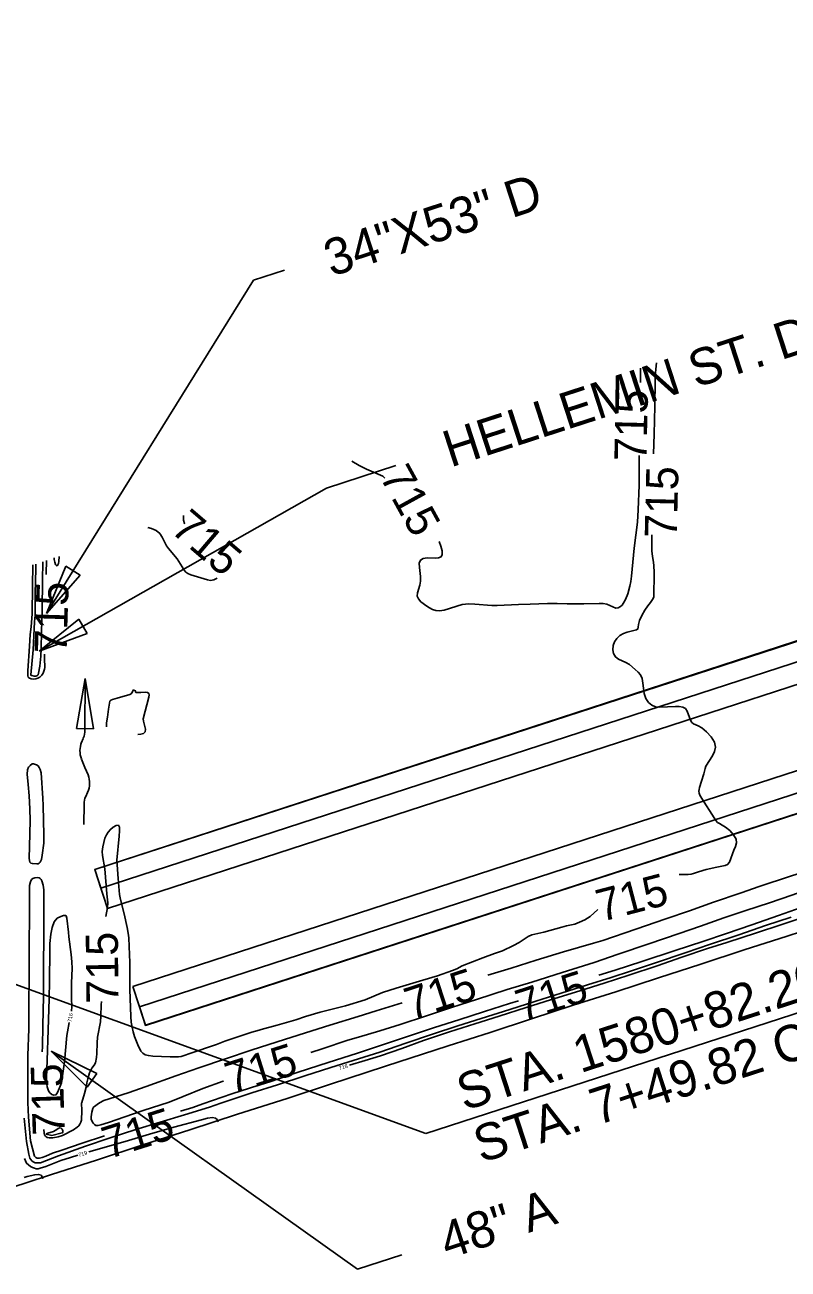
# Model space of a CAD drawing. Extents: x -468563856 to 36492962, y -306094093 to 11899197.
# Drawn here: x 1824382 to 1825166, y 531760 to 533036 of the extents above; entities that cross this region are included whole.
import ezdxf

# ---------------------------------------------------------------- set-up
doc = ezdxf.new("R2010")
doc.units = 0
for name, color, linetype in [('Default', 7, 'Continuous'), ('DT_X_Contour_Minor', 7, 'Continuous'), ('Level 14', 7, 'Continuous'), ('Level 19', 7, 'Continuous'), ('Level 31', 7, 'Continuous'), ('Level 40', 7, 'Continuous'), ('SC_Shading3', 7, 'Continuous')]:
    doc.layers.add(name, color=color, linetype=linetype)

msp = doc.modelspace()

# ---------------------------------------------------------------- linework, layer by layer
at = {"layer": 'Default'}
for points in [[(1824453.9, 532170), (1824460.1, 532150.9), (1827123.3, 533015.5), (1827116.5, 533036.4)], [(1824499.7, 532029.1), (1824505.9, 532010), (1827169, 532874.6), (1827162.8, 532893.7)]]:
    msp.add_lwpolyline(points, close=True, dxfattribs=at)
at = {"layer": 'DT_X_Contour_Minor'}
for points in [[(1825030.7, 532689.6), (1825029.7, 532679.8), (1825029.2, 532671), (1825028.7, 532645.4), (1825028.2, 532616.5), (1825027.6, 532596.3)], [(1825014, 532669.6), (1825014.2, 532677.5), (1825014.3, 532684.3)], [(1825013.6, 532650.8), (1825013.6, 532651.6)], [(1824717.8, 532588.8), (1824725.2, 532584.3), (1824732.7, 532580.6), (1824749.7, 532573.6), (1824751.8, 532571.3)], [(1824807.5, 532506.3), (1824809.3, 532501.7), (1824810.6, 532496.8), (1824810.6, 532493.2), (1824809.4, 532490.8), (1824806.9, 532489.7), (1824803.5, 532489.4), (1824795, 532489.6), (1824791, 532489), (1824788.1, 532487.3), (1824787, 532484.1), (1824787.1, 532479.9), (1824788.1, 532470.4), (1824788.2, 532465.8), (1824787.6, 532461.5), (1824785.1, 532453.8), (1824784.8, 532450.5), (1824786.1, 532447.5), (1824788.6, 532444.7), (1824794.6, 532440.1), (1824797.6, 532438.3), (1824800.6, 532436.8), (1824804, 532435.8), (1824807.9, 532435.4), (1824812.6, 532436.1), (1824831.2, 532441.7), (1824837.8, 532442.4), (1824844.2, 532442.3), (1824861.6, 532440.9), (1824866.9, 532440.8), (1824888.9, 532441.9), (1824900.8, 532442), (1824918.5, 532443), (1824928.5, 532442.7), (1824938.8, 532442.4), (1824956.1, 532442.6), (1824971.6, 532443), (1824975.7, 532442.8), (1824979.4, 532442), (1824988.9, 532438), (1824991.3, 532438.3), (1824993.5, 532439.6), (1824995.2, 532441.2), (1824996.5, 532442.9), (1824998.7, 532446.9), (1825001.1, 532452.9), (1825003.3, 532460.7), (1825004.2, 532465.3), (1825004.9, 532470.8), (1825007.7, 532499.6), (1825010.9, 532526.4), (1825011.7, 532538.9), (1825012.6, 532564.3), (1825012.7, 532579.1), (1825012.7, 532594.6)], [(1824546.2, 532524.5), (1824545.9, 532524.8), (1824545.1, 532528.3), (1824545.1, 532533)], [(1824508.2, 532520.9), (1824512.2, 532519.8), (1824517, 532517.6), (1824520.5, 532514.5), (1824522.9, 532510.9), (1824527.5, 532501.9), (1824529.5, 532499.3), (1824538.5, 532488.6), (1824543.6, 532480.3), (1824545.6, 532477), (1824547.4, 532474.9), (1824549.4, 532473.5), (1824552.3, 532472.4), (1824569.7, 532467), (1824572.8, 532466.5), (1824576, 532467.1), (1824579.5, 532468.8)], [(1825025.8, 532513.2), (1825025.7, 532505.2), (1825025.9, 532496.7), (1825026.4, 532491.2), (1825027.2, 532487.2), (1825027.8, 532482.1), (1825028.1, 532474.4), (1825027.8, 532449.6), (1825027.3, 532447.8), (1825024.4, 532444), (1825021.8, 532440.6), (1825018.6, 532435.9), (1825015.5, 532430.4), (1825013.1, 532425.3), (1825012.2, 532421.3), (1825011.9, 532418.5), (1825011.4, 532416.7), (1825009.9, 532415.7), (1825000.5, 532413.5), (1824996.6, 532412), (1824993, 532409.9), (1824989.9, 532407), (1824987.6, 532403.5), (1824986.1, 532399.6), (1824985.7, 532395.4), (1824986.4, 532391.4), (1824988.3, 532388.1), (1824991.4, 532385.8), (1824999.2, 532382.3), (1825002.7, 532380.2), (1825008.8, 532375.1), (1825011.6, 532372.5), (1825014.1, 532369.5), (1825015.8, 532365.8), (1825016.6, 532361.2), (1825017.1, 532355.9), (1825017.9, 532350.5), (1825019.7, 532345.5), (1825022.3, 532341.3), (1825025.7, 532338.4), (1825029.6, 532336.9), (1825033.7, 532336.6), (1825050.1, 532337.1), (1825054, 532337.1), (1825057.6, 532336.5), (1825060.4, 532335.1), (1825062.2, 532332.5), (1825065.5, 532323.1), (1825067, 532320.9), (1825068.7, 532319.5), (1825073.4, 532317.4), (1825077.1, 532315.2), (1825081.8, 532311.2), (1825086.6, 532306.2), (1825090, 532300.7), (1825091, 532295.6), (1825090.2, 532291), (1825088.1, 532286.6), (1825081.3, 532276), (1825080.4, 532273.5), (1825079.3, 532268.2), (1825076.9, 532260.6), (1825074.7, 532254.1), (1825074.2, 532251.9), (1825074.1, 532250.2), (1825074.3, 532248.4), (1825075.2, 532246.2), (1825077.1, 532242.8), (1825089.7, 532223.1), (1825091.4, 532220.3), (1825093.1, 532218.3), (1825095.1, 532217), (1825097.9, 532215.6), (1825101.4, 532213.3), (1825105.7, 532209.8), (1825109.7, 532205.5), (1825112.3, 532201.1), (1825112.7, 532197.2), (1825111.5, 532193.6), (1825109.8, 532189.7), (1825105.4, 532177.4), (1825103.6, 532175.1), (1825101, 532173.9), (1825092.4, 532172.2), (1825081.6, 532170.1), (1825073.7, 532167.7), (1825068.5, 532165.8), (1825066, 532165.2), (1825063.1, 532164.9), (1825053.9, 532164.7)], [(1824393.2, 532483.3), (1824393.2, 532478.3), (1824392.8, 532453.2), (1824392.7, 532430.7), (1824392.1, 532424.1), (1824390.7, 532395.4), (1824388.2, 532369.7), (1824388.5, 532369.1), (1824389.3, 532368.8), (1824391.7, 532368.4), (1824393.5, 532368.4), (1824395, 532369), (1824395.6, 532369.7), (1824396.1, 532371.2), (1824397.3, 532378.5), (1824398.4, 532388.7), (1824398.7, 532396.5), (1824399.3, 532413.7), (1824400, 532436.7), (1824400.2, 532466.5), (1824400.5, 532485.7)], [(1824403.9, 532472.6), (1824403.9, 532473.6), (1824404.2, 532486.9)], [(1824412.3, 532489.6), (1824412.3, 532488.1), (1824412.8, 532485.2), (1824413.6, 532483), (1824414.4, 532481.7), (1824415.2, 532481.6), (1824416, 532482.5), (1824416.6, 532484), (1824417, 532486), (1824417.4, 532490.9), (1824417.4, 532491.2)], [(1824390.3, 532482.4), (1824389.9, 532460.7), (1824389.5, 532432.4), (1824388.4, 532419), (1824387.6, 532411.1), (1824386.8, 532398.9), (1824385.1, 532373.9), (1824385.2, 532368.6), (1824385.5, 532367.4), (1824386.2, 532366.7), (1824388.4, 532365.7), (1824390.6, 532365.2), (1824393.3, 532365.5), (1824395.4, 532366.1), (1824397.6, 532367.3), (1824399.4, 532369.2), (1824400.8, 532371.5), (1824402.3, 532375.3), (1824402.6, 532377.3), (1824402.4, 532386.4), (1824402.4, 532390.9)], [(1824465.9, 532316.4), (1824465.9, 532316.4), (1824466, 532320.4), (1824466.8, 532326.2), (1824468.1, 532334.3), (1824469.2, 532342.7), (1824470.5, 532343.5), (1824472.2, 532344.3), (1824476.8, 532345.8), (1824489.9, 532349.4), (1824491.1, 532350.3), (1824492.5, 532352.1), (1824493.2, 532353.9), (1824493.2, 532354.1), (1824494, 532354), (1824495.7, 532353.2), (1824495.7, 532352.3), (1824496.1, 532351.7), (1824497.1, 532351.4), (1824501.3, 532351.6), (1824506.1, 532351.8), (1824508, 532351.4), (1824509.2, 532350.6), (1824509.6, 532349), (1824509.3, 532346.6), (1824503.6, 532324.5), (1824503.8, 532322.1), (1824505.9, 532313.9), (1824505.5, 532311.3), (1824503.8, 532309.6), (1824501, 532308.7), (1824498.2, 532308.5)], [(1824401.6, 532197), (1824401.5, 532205.3), (1824401, 532235.6), (1824400.6, 532243.2), (1824398.7, 532269.2), (1824397.7, 532272.7), (1824396.8, 532274.7), (1824395.6, 532276.4), (1824393.9, 532277.4), (1824390.9, 532278.2), (1824389.5, 532278.2), (1824387.4, 532276.8), (1824385.9, 532275.1), (1824384.8, 532272.1), (1824384.5, 532267.6), (1824385.3, 532257.3), (1824386.5, 532245.5), (1824387.2, 532232.1), (1824387.4, 532220.3), (1824386.9, 532193.7), (1824386.6, 532181.6), (1824386.8, 532179.1), (1824387.3, 532177.5), (1824388.3, 532176.5), (1824389.9, 532176), (1824394.4, 532175.7), (1824395.7, 532175.9), (1824396.7, 532176.3), (1824397.9, 532177.6), (1824399, 532180.2), (1824400, 532184.5), (1824401.6, 532197)], [(1824970.3, 532128.8), (1824962.3, 532121.8), (1824957, 532118.4), (1824951.6, 532115.8), (1824946.6, 532114), (1824938, 532112), (1824933.2, 532110.9), (1824914.9, 532105.5), (1824902.7, 532103), (1824898.9, 532101.1), (1824889.5, 532095.2), (1824883.6, 532092), (1824872.3, 532086.6), (1824864.4, 532083.7), (1824852.3, 532079.3), (1824830.9, 532071.1), (1824825.7, 532068.2), (1824821.1, 532066.3), (1824805.7, 532061), (1824790.8, 532056.4), (1824763.3, 532048.1), (1824749.2, 532043.7), (1824731.3, 532036.1), (1824711.1, 532030.2), (1824685.2, 532023.6), (1824670.2, 532019.3), (1824660.1, 532015.7), (1824641.1, 532010.1), (1824624.6, 532005.7), (1824622.6, 532005.3), (1824615.2, 532003), (1824587.5, 531993.9), (1824578.7, 531990.5), (1824575.7, 531989.3), (1824554.5, 531982.1), (1824542.4, 531978.2), (1824539.6, 531977.7), (1824531.4, 531977.9), (1824513.3, 531978.6), (1824508.9, 531979), (1824505.5, 531979.9), (1824503.1, 531981.5), (1824501.3, 531983.7), (1824498.1, 531990.2), (1824494.7, 531998.7), (1824493.3, 532003.3), (1824492.1, 532008.2), (1824491.3, 532013.5), (1824490.8, 532019.3), (1824489.8, 532046.8), (1824489.9, 532074.5), (1824489.3, 532090.8), (1824488.7, 532099.9), (1824488.1, 532104.7), (1824487.1, 532110.5), (1824483.9, 532124.6), (1824480.1, 532139.1), (1824479.3, 532144.4), (1824478, 532160.8), (1824476.6, 532179.4), (1824478.8, 532204.3), (1824479.2, 532209.7), (1824479.2, 532213.5), (1824478.2, 532215.4), (1824475.9, 532215.2), (1824472.8, 532213.4), (1824469.9, 532211), (1824467.5, 532208.4), (1824465.8, 532205.5), (1824464.3, 532202), (1824463, 532197.8), (1824462, 532193.1), (1824461.6, 532188.5), (1824461.8, 532184.4), (1824464.2, 532170.5), (1824466.3, 532145), (1824467.1, 532135.9), (1824466.8, 532131.1), (1824465.2, 532121.8)], [(1825294.3, 532204.6), (1825267.4, 532195.2), (1825252.1, 532190.1), (1825225.1, 532181.4), (1825201.2, 532173.8), (1825168, 532163.2), (1825135.9, 532152.4), (1825117.5, 532146.1), (1825089.2, 532136.3), (1825064.5, 532127.7), (1825040.2, 532119.3), (1825009.5, 532108.7), (1824975.4, 532097.2), (1824965.9, 532094.3), (1824935.2, 532085.6), (1824907, 532077), (1824881.2, 532068.9), (1824857.3, 532061.4)], [(1824971.2, 532061.4), (1824988, 532066.8), (1825015.5, 532075.7), (1825049.8, 532086.9), (1825078, 532096.2), (1825102.3, 532104.2), (1825128.5, 532113.1), (1825155.7, 532122.9), (1825173.4, 532129), (1825200.8, 532137.9), (1825227.3, 532146.3), (1825257.6, 532155.7), (1825283.3, 532163.7), (1825312.1, 532172.7), (1825317.1, 532174.3)], [(1824400, 531982.8), (1824400.1, 531988.5), (1824400.6, 532009.5), (1824401.2, 532039.9), (1824401.3, 532073), (1824401.5, 532100), (1824401.6, 532127.3), (1824401.4, 532149), (1824400.8, 532153.8), (1824399.5, 532158.3), (1824398.7, 532159.8), (1824397.9, 532160.8), (1824396.9, 532161.4), (1824394.6, 532161.7), (1824392.3, 532161.5), (1824390.2, 532160.8), (1824388.8, 532159.6), (1824387.7, 532157.3), (1824387, 532153.7), (1824386.8, 532144.7), (1824386.7, 532124.2), (1824386.4, 532092.1), (1824386.4, 532059.9), (1824386.3, 532031.7), (1824386, 532006.6), (1824385.2, 531979), (1824385, 531960), (1824385.2, 531931.1), (1824385.7, 531916), (1824387.8, 531891.6), (1824392, 531875.9), (1824393.5, 531874.5), (1824394.6, 531874), (1824397, 531873.9), (1824400, 531874.5), (1824403.6, 531876), (1824410.3, 531878.8), (1824420, 531882.1), (1824440.9, 531889.2), (1824463.7, 531896.8)], [(1824675.7, 531982.2), (1824687.4, 531986), (1824713.8, 531994.8), (1824724.6, 531998), (1824746.6, 532004.3), (1824767.4, 532011), (1824794.4, 532020), (1824820.2, 532028.4), (1824845.8, 532036.7), (1824877.2, 532046.7), (1824902.6, 532054.5), (1824933.7, 532064.3), (1824966.4, 532074.7), (1824991.3, 532083), (1825022.8, 532093.6), (1825053.9, 532104.4), (1825075.6, 532111.9), (1825099.8, 532120.5), (1825122.2, 532127.8), (1825146.5, 532135.7), (1825169.4, 532143.7), (1825186, 532149.3)], [(1824715.4, 531969.2), (1824731.5, 531974), (1824747.1, 531978.9), (1824769, 531986.5), (1824791.5, 531994.4), (1824818.2, 532003.5), (1824843.9, 532011.5), (1824869, 532019.5), (1824896.9, 532028.5), (1824921.9, 532036.3), (1824951.7, 532045.5), (1824977, 532053.4), (1825002.3, 532061.5), (1825031.2, 532071.3), (1825056.4, 532080), (1825082.8, 532088.8), (1825102.7, 532095.1), (1825133.1, 532105), (1825158.2, 532113.2), (1825183.8, 532121.7), (1825210.8, 532130.8), (1825215.4, 532132.3)], [(1825168.8, 532121), (1825142.6, 532112.4), (1825115.1, 532103), (1825085, 532092.9), (1825060.9, 532084.8), (1825029.4, 532074.3), (1825004.9, 532066), (1824983.9, 532059.1), (1824959.7, 532051.5), (1824932.6, 532043), (1824906.7, 532035), (1824879.9, 532026.5), (1824850.7, 532017.2), (1824826.5, 532009.6), (1824800.6, 532001.1), (1824773.3, 531991.9), (1824746.6, 531982.7), (1824719.1, 531973.9), (1824696.1, 531966.7), (1824669.4, 531958.2), (1824641.5, 531949.2), (1824615.2, 531940.8), (1824583.4, 531930.2), (1824571.5, 531926.3), (1824545.8, 531918.4), (1824521.1, 531910.8), (1824496.1, 531903.1), (1824468.7, 531894.2), (1824444.4, 531886.1), (1824416.7, 531876.3), (1824398.1, 531869.1), (1824394.5, 531868.9), (1824392.5, 531869.2), (1824390.7, 531870), (1824389.2, 531871.1), (1824388.1, 531872.5), (1824387.3, 531874), (1824386.3, 531877.8), (1824383.6, 531891), (1824381.4, 531914.8)], [(1824429.8, 532024.7), (1824430.2, 532029.3), (1824430.1, 532037.5), (1824429.8, 532053.8), (1824430.5, 532068.4), (1824430.4, 532075.4), (1824429.7, 532082.6), (1824427.3, 532100.9), (1824427, 532105.5), (1824425.2, 532120), (1824424.6, 532122.3), (1824423.7, 532122.9), (1824421.8, 532122.6), (1824418.9, 532121.8), (1824415.3, 532119.9), (1824412.2, 532116.2), (1824410, 532110.4), (1824408.7, 532103.7), (1824407.7, 532094), (1824407.6, 532086.1), (1824407.5, 532055.7), (1824407.1, 532037.2), (1824406, 532005.4), (1824404.8, 531974.1), (1824404.4, 531956.6), (1824404.6, 531949.7), (1824405, 531947.1), (1824405.5, 531944.8), (1824406.4, 531942.8), (1824407.8, 531940.9), (1824409.7, 531939.3), (1824411.9, 531938.4), (1824413.9, 531938.7), (1824415.4, 531940.4), (1824417.6, 531945.9), (1824419, 531949.5), (1824419.8, 531951), (1824422.8, 531972.7), (1824425.3, 531999.7), (1824425.9, 532003.4), (1824427.7, 532012.9)], [(1824460.7, 532034.5), (1824460.5, 532031.2), (1824460.1, 532019.4), (1824459.6, 532013.6), (1824456.7, 531997.8), (1824456.3, 531992.1), (1824456, 531981.2), (1824455.6, 531977.1), (1824454.5, 531971.7), (1824453.2, 531969.2), (1824450.8, 531966), (1824448.6, 531961.2), (1824446.6, 531955.2), (1824445.8, 531951.1), (1824444.9, 531946.5), (1824443.3, 531940.3), (1824440.4, 531931.1), (1824440.1, 531930.1), (1824440.5, 531922.7), (1824440.1, 531912.8), (1824439.6, 531910.7), (1824438.6, 531908.8), (1824437.4, 531907.1), (1824435.8, 531905.6), (1824432, 531903), (1824420.6, 531897), (1824416.1, 531895.8), (1824410.7, 531894.7), (1824407.2, 531894.6), (1824404.9, 531895.2), (1824403.2, 531896.4), (1824402.4, 531897.6), (1824402, 531899.4), (1824401.7, 531903.3)], [(1824769.6, 532033.3), (1824742.6, 532024.8), (1824724.3, 532019.1), (1824695.2, 532010.2), (1824670.2, 532002.4), (1824641, 531993.3), (1824614.5, 531984.7), (1824588.2, 531975.8), (1824560.6, 531966.4), (1824537.1, 531958.4), (1824506.6, 531947.5), (1824488.2, 531940.9), (1824463.1, 531933), (1824458.6, 531930.6), (1824452.4, 531926.1), (1824451.7, 531924.8), (1824450.8, 531921.1), (1824450.2, 531916.3), (1824450.3, 531913.8), (1824451.2, 531911.5), (1824452.1, 531909.9), (1824453.4, 531908.5), (1824455, 531907.5), (1824457.3, 531907.3), (1824460.1, 531907.9), (1824468.1, 531910.4), (1824484.8, 531916.2), (1824503.6, 531922.7), (1824530.2, 531931.4), (1824544.7, 531937), (1824564.9, 531945.4), (1824585.5, 531952.8), (1824586, 531953)], [(1824541.8, 531921.9), (1824554.4, 531925.9), (1824564.7, 531929.4), (1824594.4, 531939.8), (1824612.6, 531945.7), (1824639.4, 531954.2), (1824662.7, 531962), (1824693.5, 531972.1), (1824723.6, 531981.7), (1824754.3, 531991.7), (1824780.2, 532000.3), (1824802.6, 532007.8), (1824827.6, 532015.9), (1824854, 532024.2), (1824879.8, 532032.4), (1824889, 532035.3)], [(1824447.9, 531880.2), (1824456.2, 531882.7), (1824488.5, 531892.1), (1824510, 531898.5), (1824534.9, 531905.5), (1824563.3, 531913.3), (1824569.5, 531914.7), (1824574.8, 531915.4), (1824577.9, 531914.9), (1824579.5, 531913.5), (1824580.5, 531911.1)], [(1824409.7, 531897.2), (1824404, 531898.5), (1824404.2, 531898.9), (1824405.6, 531899.5), (1824411.5, 531901.3), (1824414.8, 531903.3), (1824416.4, 531904.3), (1824417.9, 531904.9), (1824419.2, 531904.6), (1824420.2, 531903.7), (1824421.2, 531901.7), (1824421.2, 531900.3), (1824420.3, 531899.9), (1824409.7, 531897.2)], [(1824381.6, 531873.6), (1824383.8, 531868.6), (1824387.7, 531865.4), (1824389.8, 531864.1), (1824391.8, 531863.4), (1824393.7, 531863), (1824395.7, 531863), (1824397.7, 531863.4), (1824403.6, 531865.4), (1824418.9, 531871.3), (1824428.8, 531874.5), (1824436.4, 531876.8)], [(1824400.8, 531852.8), (1824400.7, 531852.9), (1824400, 531854.7), (1824398.7, 531856.4), (1824396.2, 531857.2), (1824392.3, 531856.9), (1824384.3, 531854.9), (1824381.2, 531854.1)]]:
    msp.add_lwpolyline(points, dxfattribs=at)
at = {"layer": 'Level 14'}
msp.add_lwpolyline([(1825208.8, 532115.9), (1825164.8, 532101.6), (1825120.5, 532087.4), (1825076, 532072.9), (1825032.5, 532058.8), (1824988.8, 532044.6), (1824944.9, 532030.7), (1824902.3, 532016.8), (1824859.9, 532002.9), (1824816.5, 531989), (1824752.2, 531968.1), (1824694.8, 531949.4), (1824651.3, 531935.1), (1824600.5, 531918.9), (1824551.6, 531903), (1824503.3, 531887.4), (1824455.5, 531871.7), (1824409.5, 531857), (1824382.3, 531848.2), (1824332.1, 531832.1)], dxfattribs=at)
at = {"layer": 'Level 31'}
for p, q in [((1824435.2, 532314.5), (1824444.1, 532366)), ((1824443.8, 532313.1), (1824444.1, 532366)), ((1824444.1, 532366), (1824452.4, 532314.4)), ((1824452.4, 532314.4), (1824435.2, 532314.5)), ((1824442, 532304.5), (1824440.3, 532300.4)), ((1824440.2, 532283.3), (1824443.7, 532274.7)), ((1824443.7, 532274.7), (1824446.9, 532267)), ((1824446.5, 532249.1), (1824444.5, 532244.9)), ((1824442.7, 532216), (1824442.8, 532237))]:
    msp.add_line(p, q, dxfattribs=at)
for centre, radius, start, end in [((1824421.4, 532313.2), 22.4, 337.3227, 359.6827), ((1824461, 532291.8), 22.4, 157.2839, 202.1277), ((1824426.2, 532258.5), 22.4, 335.15, 22.2585), ((1824462, 532236.9), 19.2, 155.1999, 179.6827)]:
    msp.add_arc(centre, radius, start, end, dxfattribs=at)
at = {"layer": 'Level 40'}
for p, q in [((1824616.9, 532774.6), (1824648.5, 532784.9)), ((1824616.9, 532774.6), (1824404.3, 532432.7)), ((1824404.3, 532432.7), (1824424.3, 532481)), ((1824438.9, 532471.9), (1824404.3, 532432.7)), ((1824424.3, 532481), (1824438.9, 532471.9)), ((1824396.7, 532394), (1824437.4, 532426.9)), ((1824437.4, 532426.9), (1824445.9, 532411.9)), ((1824445.9, 532411.9), (1824396.7, 532394)), ((1824793.6, 531899), (1825580.4, 532154.4)), ((1824367.9, 532053.6), (1824793.6, 531899)), ((1824723.6, 531760), (1824409.1, 531983.7)), ((1824446.1, 531946.8), (1824409.1, 531983.7)), ((1824409.1, 531983.7), (1824456.1, 531960.8)), ((1824456.1, 531960.8), (1824446.1, 531946.8)), ((1824723.6, 531760), (1824769, 531774.8))]:
    msp.add_line(p, q, dxfattribs=at)
msp.add_lwpolyline([(1824396.8, 532394), (1824691.8, 532561.3), (1824763.1, 532584.4)], dxfattribs=at)
at = {"layer": 'SC_Shading3'}
for points in [[(1824466.9, 532129.9), (1824453.9, 532170), (1827117.1, 533034.5), (1827130.1, 532994.5)], [(1824492.9, 532050), (1824505.8, 532010.1), (1827169, 532874.7), (1827156, 532914.7)]]:
    msp.add_lwpolyline(points, close=True, dxfattribs=at)

# ---------------------------------------------------------------- texts
at = {"layer": 'Level 19'}
for s, height, rotation, p in [('715', 33, 88.7053, (1825020.2, 532588.4)), ('715', 33, 298.8204, (1824745.8, 532573.3)), ('715', 33, 88.6538, (1825051.4, 532509.7)), ('715', 33, 319.4486, (1824530.4, 532516.9)), ('715', 33, 88.3043, (1824424.9, 532391.1)), ('715', 33, 14.6219, (1824973.7, 532116.1)), ('715', 33, 90.619, (1824478.3, 532032.5)), ('715', 33, 18.0023, (1824778.6, 532015.4)), ('715', 33, 17.8648, (1824892.6, 532013.3)), ('716', 4, 79.3432, (1824429.8, 532013.2)), ('715', 33, 17.4638, (1824594.1, 531938.9)), ('715', 33, 91.8222, (1824423.2, 531897.8)), ('718', 4, 16.4725, (1824705.2, 531964.1)), ('715', 33, 17.5841, (1824467.8, 531872.7)), ('719', 4, 16.6788, (1824437.6, 531875.1))]:
    msp.add_text(s, height=height, rotation=rotation, dxfattribs=at).set_placement(p)
at = {"layer": 'Level 40'}
for s, p in [('34"X53" D', (1824696.8, 532777.9)), ('HELLEMIN ST. DT.', (1824819.1, 532582.2)), ('STA. 1580+82.20 U.S. 24 =', (1824833.2, 531922.2)), ('STA. 7+49.82 C.R.-133', (1824850.5, 531868.7)), ('48" A', (1824815.8, 531770))]:
    msp.add_text(s, height=37.5, rotation=17.9864, dxfattribs=at).set_placement(p)

doc.saveas('drawing.dxf')
